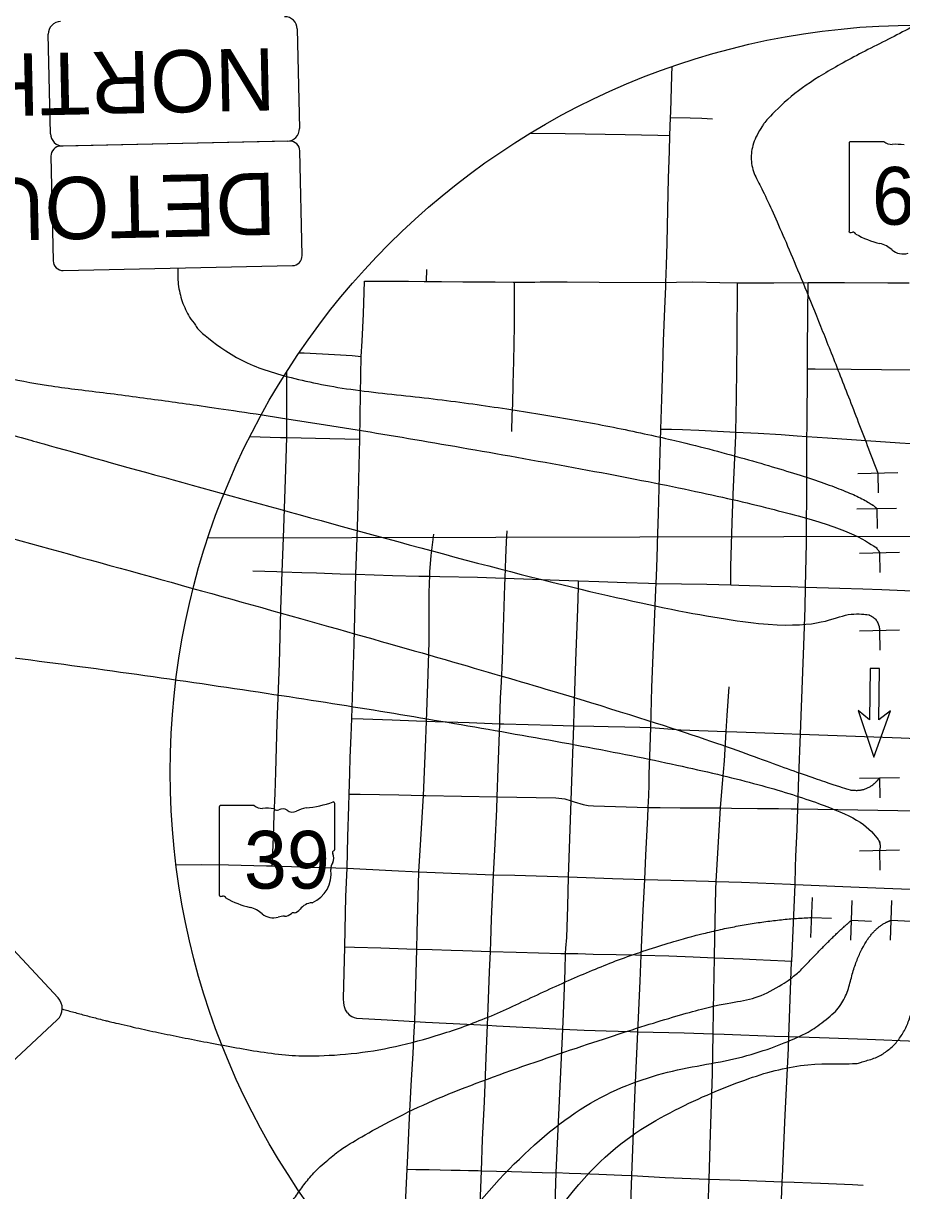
# Model space of a CAD drawing. Extents: x -15.3 to 34, y 0 to 22.
# Drawn here: x 5.535 to 9.062, y 14.569 to 19.257 of the extents above; entities that cross this region are included whole.
import ezdxf

# ---------------------------------------------------------------- set-up
doc = ezdxf.new("R2010")
doc.units = 0
for name, color, linetype in [('GM_X_City_Street', 7, 'Continuous'), ('GM_X_State_Route', 7, 'Continuous'), ('GM_X_State_Shield', 7, 'Continuous'), ('GM_X_Township', 7, 'Continuous'), ('PM_P_Cells', 7, 'Continuous'), ('SH_Text', 7, 'Continuous'), ('SN_P_Signs', 7, 'Continuous')]:
    doc.layers.add(name, color=color, linetype=linetype)

msp = doc.modelspace()

# ---------------------------------------------------------------- linework, layer by layer
at = {"layer": 'GM_X_City_Street'}
for p, q in [((7.1544, 18.2223), (7.1554, 18.2682)), ((6.5927, 17.5937), (6.5924, 17.8581))]:
    msp.add_line(p, q, dxfattribs=at)
for points in [[(8.1336, 18.8786), (8.1343, 18.9019), (8.1389, 19.0477), (8.1398, 19.0836)], [(8.1313, 18.8064), (8.1336, 18.8786)], [(8.1336, 18.8786), (8.2121, 18.8776), (8.2599, 18.8759), (8.3015, 18.8744)], [(7.5709, 18.8161), (7.7102, 18.8143), (7.9514, 18.8108), (8.0831, 18.8076), (8.1313, 18.8064)], [(8.1228, 18.5094), (8.1256, 18.6353), (8.1293, 18.7435), (8.1313, 18.8064)], [(8.1149, 18.2169), (8.1175, 18.2866), (8.1198, 18.3737), (8.1228, 18.5094)], [(6.8918, 17.9196), (6.8949, 17.9808), (6.9005, 18.0899), (6.9035, 18.1771), (6.9044, 18.2223)], [(6.9044, 18.2223), (6.9438, 18.222), (7.0203, 18.2215), (7.0809, 18.2211), (7.1446, 18.2206), (7.2143, 18.2201), (7.2992, 18.2195), (7.3689, 18.219), (7.4296, 18.2186), (7.5016, 18.2181), (7.5069, 18.2181)], [(7.4963, 17.6178), (7.4979, 17.6838), (7.5002, 17.7276), (7.5023, 17.8089), (7.5046, 17.8998), (7.5064, 17.9695), (7.5066, 18.0423), (7.5069, 18.1858), (7.5069, 18.2181)], [(7.5069, 18.2181), (7.5892, 18.2183), (7.6102, 18.2188), (7.7184, 18.2195), (7.8471, 18.2175), (8.1149, 18.2169)], [(8.0952, 17.6279), (8.0987, 17.7474), (8.1025, 17.8753), (8.1058, 17.9811), (8.1108, 18.1118), (8.1143, 18.1992), (8.1149, 18.2169)], [(8.1149, 18.2169), (8.1577, 18.2175), (8.2227, 18.2185), (8.3311, 18.2157), (8.4029, 18.2155)], [(8.3958, 17.6158), (8.3988, 17.7546), (8.4008, 17.9799), (8.4029, 18.2155)], [(8.4029, 18.2155), (8.5486, 18.2151), (8.6858, 18.2157)], [(8.6834, 17.8697), (8.6839, 17.9505), (8.6858, 18.2157)], [(8.6858, 18.2157), (8.8324, 18.2164), (9.0062, 18.2151), (9.0924, 18.2147)], [(6.6426, 17.9345), (6.6623, 17.934), (6.7843, 17.9274), (6.8552, 17.9225), (6.8918, 17.9196)], [(6.8862, 17.587), (6.8892, 17.7697), (6.8918, 17.9196)], [(8.6815, 17.5982), (8.6818, 17.6358), (8.6834, 17.8697)], [(8.6834, 17.8697), (8.714, 17.8694), (8.8594, 17.868), (8.9809, 17.8668), (9.0968, 17.8657)], [(6.4445, 17.5972), (6.568, 17.5943), (6.5927, 17.5937)], [(6.5744, 17.0543), (6.579, 17.191), (6.5869, 17.4253), (6.5927, 17.5937)], [(6.5927, 17.5937), (6.7658, 17.5895), (6.8862, 17.587)], [(6.875, 17.1923), (6.8792, 17.3197), (6.8862, 17.587)], [(8.0758, 17.0079), (8.0783, 17.0705), (8.0812, 17.1578), (8.0815, 17.1671), (8.0852, 17.2887), (8.0897, 17.4416), (8.0952, 17.6279)], [(8.0952, 17.6279), (8.1376, 17.6272), (8.1813, 17.6265), (8.2472, 17.6232), (8.3712, 17.6171), (8.3958, 17.6158)], [(8.3755, 17.0021), (8.3758, 17.0323), (8.3762, 17.0759), (8.3786, 17.1637), (8.381, 17.2515), (8.3847, 17.3651), (8.3955, 17.6016), (8.3958, 17.6158)], [(8.3958, 17.6158), (8.4861, 17.6114), (8.5774, 17.6052), (8.6427, 17.6009), (8.6815, 17.5982)], [(8.6759, 16.993), (8.6799, 17.1711), (8.6804, 17.4328), (8.6815, 17.5982)], [(8.6815, 17.5982), (8.7641, 17.5927), (9.055, 17.5722), (9.098, 17.5703), (9.0993, 17.5703)], [(7.4698, 17.0283), (7.4724, 17.1095), (7.4749, 17.1749), (7.4778, 17.2184)], [(6.8705, 17.0443), (6.8725, 17.1155), (6.875, 17.1917), (6.875, 17.1923)], [(7.1667, 17.0362), (7.1675, 17.0543), (7.1729, 17.1196), (7.1778, 17.1628), (7.1807, 17.1843), (7.1836, 17.2058)], [(6.4567, 17.0582), (6.5522, 17.055), (6.5744, 17.0543)], [(6.5345, 15.8728), (6.5366, 15.9255), (6.5392, 15.9913), (6.5422, 16.0779), (6.5455, 16.1634), (6.5488, 16.2501), (6.5545, 16.4459), (6.5632, 16.6858), (6.5693, 16.9035), (6.5744, 17.0543)], [(6.5744, 17.0543), (6.6537, 17.0516), (6.7116, 17.0496), (6.8069, 17.0465), (6.8705, 17.0443)], [(6.8533, 16.4652), (6.8629, 16.7651), (6.8705, 17.0443)], [(6.8705, 17.0443), (7.017, 17.0394), (7.1234, 17.0365), (7.1601, 17.0362), (7.1667, 17.0362)], [(7.1535, 16.4546), (7.1593, 16.6032), (7.1639, 16.7715), (7.1646, 16.9667), (7.1655, 17.0107), (7.1667, 17.0362)], [(7.1667, 17.0362), (7.2078, 17.0359), (7.3591, 17.0334), (7.4667, 17.0283), (7.4698, 17.0283)], [(7.4477, 16.4442), (7.4483, 16.4595), (7.4513, 16.5464), (7.4543, 16.612), (7.4591, 16.6983), (7.4634, 16.8295), (7.4689, 17.0003), (7.4698, 17.0283)], [(7.4698, 17.0283), (7.5796, 17.0245), (7.6869, 17.021), (7.7643, 17.0183)], [(7.7451, 16.4359), (7.7471, 16.494), (7.754, 16.6965), (7.7611, 16.9042), (7.7629, 16.9482), (7.7638, 16.9922), (7.7643, 17.0183)], [(7.7643, 17.0183), (7.8458, 17.0156), (7.9558, 17.0119), (8.0456, 17.0089), (8.0758, 17.0079)], [(8.0539, 16.4291), (8.0584, 16.5902), (8.0634, 16.7213), (8.0748, 16.9832), (8.0758, 17.0079)], [(8.0758, 17.0079), (8.28, 17.0049), (8.3755, 17.0021)], [(8.3755, 17.0021), (8.4076, 17.0011), (8.5377, 16.9972), (8.6158, 16.9948), (8.6759, 16.993)], [(8.6552, 16.402), (8.6578, 16.4755), (8.6683, 16.7582), (8.674, 16.9105), (8.6759, 16.993)], [(8.6759, 16.993), (8.8134, 16.9888), (8.9053, 16.9858), (8.9824, 16.9832), (9.1055, 16.9773)], [(8.3574, 16.4126), (8.3614, 16.4766), (8.3686, 16.592)], [(6.8433, 16.1615), (6.8458, 16.2437), (6.8476, 16.3088), (6.8511, 16.3953), (6.8533, 16.4652)], [(6.8533, 16.4652), (6.8995, 16.4636), (7.0153, 16.4594), (7.1137, 16.456), (7.1535, 16.4546)], [(7.1412, 16.1561), (7.1493, 16.3478), (7.1535, 16.4546)], [(7.1535, 16.4546), (7.1892, 16.4533), (7.3252, 16.4485), (7.4477, 16.4442)], [(7.4375, 16.1509), (7.4418, 16.2653), (7.4477, 16.4442)], [(7.4477, 16.4442), (7.464, 16.4438), (7.6597, 16.4378), (7.7451, 16.4359)], [(7.7348, 16.1345), (7.7363, 16.1756), (7.7451, 16.4359)], [(7.7451, 16.4359), (7.8257, 16.4341), (7.8837, 16.4328), (7.9503, 16.4314), (8.0109, 16.4301), (8.0539, 16.4291)], [(8.0438, 16.108), (8.0462, 16.1556), (8.0476, 16.1987), (8.0484, 16.2416), (8.0518, 16.3499), (8.0539, 16.4291)], [(8.0539, 16.4291), (8.1746, 16.419), (8.3574, 16.4126)], [(8.334, 16.1058), (8.3423, 16.2046), (8.3497, 16.2955), (8.3544, 16.3658), (8.3574, 16.4126)], [(8.3574, 16.4126), (8.3997, 16.4111), (8.5873, 16.4044), (8.6552, 16.402)], [(8.6445, 16.1027), (8.6492, 16.2333), (8.6552, 16.402)], [(8.6552, 16.402), (9.0599, 16.3877), (9.1238, 16.3853)], [(6.8346, 15.8644), (6.8383, 15.9898), (6.8419, 16.1132), (6.8433, 16.1615)], [(6.8433, 16.1615), (6.8876, 16.1608), (7.0428, 16.1583), (7.1412, 16.1561)], [(7.1225, 15.8497), (7.1304, 15.9791), (7.1412, 16.1561)], [(7.1412, 16.1561), (7.1511, 16.1559), (7.4375, 16.1509)], [(7.4227, 15.8371), (7.429, 15.9612), (7.4357, 16.1015), (7.4375, 16.1509)], [(7.4375, 16.1509), (7.6725, 16.1469), (7.7096, 16.1422), (7.7348, 16.1345)], [(7.7238, 15.8286), (7.7348, 16.1345)], [(7.7348, 16.1345), (7.7469, 16.1309), (7.7825, 16.1202), (7.8033, 16.1156), (7.8245, 16.1142), (8.0438, 16.108)], [(8.0298, 15.8185), (8.0338, 15.9157), (8.0419, 16.0686), (8.0438, 16.108)], [(8.0438, 16.108), (8.0919, 16.1076), (8.1729, 16.1069), (8.2655, 16.106), (8.334, 16.1058)], [(8.3166, 15.8106), (8.334, 16.1058)], [(8.334, 16.1058), (8.3778, 16.105), (8.4832, 16.1041), (8.5676, 16.1033), (8.6175, 16.1029), (8.6445, 16.1027)], [(8.6335, 15.799), (8.6359, 15.8678), (8.6374, 15.9114), (8.6417, 16.0198), (8.6445, 16.1027)], [(8.6445, 16.1027), (9.1269, 16.0939)], [(6.8256, 15.5485), (6.8304, 15.7507), (6.8346, 15.8644)], [(7.1148, 15.5389), (7.1168, 15.6055), (7.1213, 15.8), (7.1225, 15.8497)], [(7.4102, 15.5297), (7.4116, 15.5691), (7.4147, 15.6597), (7.4227, 15.8371)], [(7.7118, 15.5217), (7.7136, 15.5431), (7.717, 15.5854), (7.7214, 15.7094), (7.7238, 15.8286)], [(8.3098, 15.5042), (8.3111, 15.586), (8.3158, 15.7794), (8.3166, 15.8106)], [(8.6202, 15.4911), (8.6335, 15.799)], [(6.8361, 15.2827), (6.8291, 15.295), (6.825, 15.3072), (6.8221, 15.3224), (6.8207, 15.3399), (6.8256, 15.5463), (6.8256, 15.5485)], [(6.8256, 15.5485), (6.8652, 15.5472), (6.9708, 15.5437), (7.0743, 15.5402), (7.1148, 15.5389)], [(7.1065, 15.2478), (7.1148, 15.5389)], [(7.1148, 15.5389), (7.1763, 15.5368), (7.2534, 15.5343), (7.2998, 15.5328), (7.4102, 15.5297)], [(7.3987, 15.2328), (7.402, 15.3035), (7.4073, 15.4474), (7.4102, 15.5297)], [(7.4102, 15.5297), (7.5134, 15.5268), (7.6925, 15.5218), (7.7118, 15.5217)], [(7.7013, 15.217), (7.7041, 15.2793), (7.711, 15.4539), (7.7118, 15.5217)], [(7.7118, 15.5217), (7.7619, 15.5206), (7.8227, 15.5192), (7.9152, 15.5172), (7.9934, 15.5155), (8.0162, 15.515)], [(8.0162, 15.515), (8.1267, 15.512), (8.2251, 15.5078), (8.3098, 15.5042)], [(8.305, 15.1986), (8.3066, 15.2949), (8.3098, 15.5042)], [(8.3098, 15.5042), (8.3119, 15.5042), (8.4243, 15.4994), (8.4769, 15.4972), (8.5924, 15.4923), (8.6202, 15.4911)], [(8.6087, 15.1879), (8.6199, 15.486), (8.6202, 15.4911)], [(6.8361, 15.2827), (6.8431, 15.2746), (6.8542, 15.2682), (6.8635, 15.2641), (6.8728, 15.262), (6.9953, 15.2549), (7.1065, 15.2478)], [(7.0763, 14.6549), (7.0788, 14.7095), (7.0858, 14.8612), (7.0927, 14.9913), (7.0997, 15.1207), (7.1043, 15.208), (7.1065, 15.2478)], [(7.1065, 15.2478), (7.1493, 15.2451), (7.3987, 15.2328)], [(7.3745, 14.6489), (7.379, 14.7742), (7.3865, 14.9255), (7.3942, 15.1385), (7.3987, 15.2328)], [(7.3987, 15.2328), (7.435, 15.2311), (7.6992, 15.2171), (7.7013, 15.217)], [(7.6749, 14.641), (7.6803, 14.7577), (7.7013, 15.217)], [(7.7013, 15.217), (7.7871, 15.2134), (7.8749, 15.2113), (7.9713, 15.2078), (8.0024, 15.2066)], [(8.0024, 15.2066), (8.1888, 15.2027), (8.305, 15.1986)], [(8.2881, 14.6152), (8.2943, 14.7955), (8.3026, 15.0395), (8.305, 15.1986)], [(8.305, 15.1986), (8.349, 15.1971), (8.5517, 15.1899), (8.6087, 15.1879)], [(8.582, 14.6041), (8.5829, 14.6256), (8.5945, 14.8734), (8.6069, 15.1395), (8.6087, 15.1879)], [(8.6087, 15.1879), (8.7321, 15.1836), (8.9236, 15.1768), (9.1233, 15.1698)], [(7.0825, 14.1005), (7.071, 14.1266), (7.0619, 14.1638), (7.0603, 14.2329), (7.0608, 14.2696), (7.0617, 14.3414), (7.0644, 14.4004), (7.0763, 14.6549)], [(7.0763, 14.6549), (7.1112, 14.6542), (7.1647, 14.6532), (7.2083, 14.6524), (7.2528, 14.6516), (7.2887, 14.6509), (7.3225, 14.6502), (7.3612, 14.6495), (7.3745, 14.6489)], [(7.3504, 14.0624), (7.354, 14.162), (7.3696, 14.5121), (7.3745, 14.6489)], [(7.3745, 14.6489), (7.4948, 14.6452), (7.6187, 14.6413), (7.6595, 14.6401), (7.6749, 14.641)], [(7.6544, 14.0516), (7.6546, 14.1018), (7.6588, 14.1886), (7.6631, 14.2974), (7.6749, 14.641)], [(7.6749, 14.641), (7.7261, 14.639), (7.7736, 14.6371), (7.8452, 14.6343), (7.9381, 14.6306), (7.9779, 14.629)], [(7.9779, 14.629), (8.1125, 14.6214), (8.2839, 14.6153), (8.2881, 14.6152)], [(8.2668, 14.0392), (8.268, 14.0683), (8.2775, 14.2857), (8.2844, 14.505), (8.2881, 14.6152)], [(8.2881, 14.6152), (8.4126, 14.6103), (8.582, 14.6041)], [(8.5503, 14.0487), (8.5572, 14.0578), (8.5621, 14.0654), (8.5642, 14.0752), (8.569, 14.282), (8.5762, 14.4615), (8.582, 14.6041)], [(8.582, 14.6041), (8.6302, 14.6026), (8.6989, 14.6004), (8.7357, 14.5992), (8.8639, 14.5933), (8.9073, 14.5913)]]:
    msp.add_lwpolyline(points, dxfattribs=at)
at = {"layer": 'GM_X_State_Route'}
for points in [[(6.1482, 15.878), (6.249, 15.8782), (6.3581, 15.8773), (6.5108, 15.8735), (6.5345, 15.8728), (6.7288, 15.8671), (6.7438, 15.8667)], [(6.7438, 15.8667), (6.8346, 15.8644), (7.0144, 15.8548), (7.1225, 15.8497), (7.2213, 15.8451), (7.4227, 15.8371), (7.5089, 15.8353), (7.7238, 15.8286)], [(7.7238, 15.8286), (7.9007, 15.8227), (8.0298, 15.8185)], [(7.937, 13.5996), (7.9371, 13.6011), (7.9474, 13.8194), (7.9499, 13.8847), (7.955, 14.0147), (7.9559, 14.0497), (7.9573, 14.1015), (7.9631, 14.2541), (7.9738, 14.5163), (7.9779, 14.629), (7.9818, 14.7347), (7.9917, 14.9734), (8.0024, 15.2066), (8.0037, 15.2353), (8.0114, 15.4102), (8.0162, 15.515), (8.0204, 15.6067), (8.0242, 15.6938), (8.0298, 15.8185)], [(8.0298, 15.8185), (8.1868, 15.8144), (8.2865, 15.8115), (8.3166, 15.8106), (8.4184, 15.8074), (8.6157, 15.7997), (8.6335, 15.799), (8.8577, 15.7893), (8.9911, 15.7839)], [(8.9911, 15.7839), (9.1313, 15.7782)]]:
    msp.add_lwpolyline(points, dxfattribs=at)
at = {"layer": 'GM_X_State_Shield'}
for p, q in [((8.8503, 18.7759), (8.8503, 18.4237)), ((8.9907, 18.782), (8.8548, 18.782)), ((6.3211, 16.1092), (6.3211, 15.757)), ((6.4616, 16.1152), (6.3257, 16.1152)), ((6.7852, 15.9397), (6.7852, 16.124)), ((6.7851, 15.9398), (6.7852, 15.9397))]:
    msp.add_line(p, q, dxfattribs=at)
for centre, radius, start, end in [((8.8556, 18.7767), 0.00538, 98.1301, 188.1301), ((9.0231, 18.8229), 0.0521, 231.6195, 271.1119), ((9.0404, 18.5842), 0.1872, 80.4867, 94.9883), ((8.8556, 18.4229), 0.00542, 171.9584, 258.3066), ((8.8564, 18.459), 0.0414, 267.339, 280.6039), ((8.8649, 18.4034), 0.0149, 29.7484, 93.2717), ((9.0533, 18.7198), 0.3554, 240.4129, 257.1985), ((8.9474, 18.2655), 0.1112, 47.1842, 75.836), ((9.0676, 18.4016), 0.0706, 230.7004, 286.2918), ((6.6199, 16.5954), 0.4921, 275.8445, 288.9065), ((6.78, 16.1247), 0.00517, 351.8621, 97.738), ((6.3264, 16.1099), 0.00538, 98.1301, 188.1301), ((6.494, 16.1561), 0.0521, 231.6195, 271.1119), ((6.5113, 15.9175), 0.1872, 80.4867, 94.9883), ((6.5538, 16.1117), 0.015, 219.7921, 297.1024), ((6.5758, 16.071), 0.0313, 54.4667, 119.1411), ((6.6162, 16.1269), 0.0376, 233.8562, 294.8282), ((6.6827, 16.0077), 0.099, 97.3462, 120.7689), ((6.784, 15.9262), 0.00799, 107.944, 210.337), ((6.7331, 15.9029), 0.048, 340.033, 23.6496), ((6.7797, 15.939), 0.00553, 289.6038, 7.7341), ((6.6475, 15.8392), 0.1231, 292.3089, 8.9858), ((6.8037, 15.8626), 0.0349, 136.8065, 186.9296), ((6.3265, 15.7562), 0.00542, 171.9584, 258.3066), ((6.3273, 15.7922), 0.0414, 267.339, 280.6039), ((6.3358, 15.7366), 0.0149, 29.7484, 93.2717), ((6.5242, 16.0531), 0.3554, 240.4129, 257.1985), ((6.6994, 15.6581), 0.0674, 94.4031, 142.5768), ((6.4183, 15.5987), 0.1112, 47.1842, 75.836), ((6.5385, 15.7349), 0.0706, 230.7004, 286.2918), ((6.5793, 15.6131), 0.058, 85.6951, 111.2099), ((6.5844, 15.7085), 0.0376, 268.777, 315.5493), ((6.6185, 15.6744), 0.0106, 65.7517, 132.6484), ((6.6139, 15.7228), 0.0398, 282.8732, 323.2771)]:
    msp.add_arc(centre, radius, start, end, dxfattribs=at)
at = {"layer": 'GM_X_Township'}
msp.add_line((6.2762, 17.1903), (11.9695, 17.2034), dxfattribs=at)
at = {"layer": 'PM_P_Cells'}
for p, q in [((8.9348, 16.6659), (8.9331, 16.4596)), ((8.9723, 16.6655), (8.9348, 16.6659)), ((8.9535, 16.6657), (8.9535, 16.6657)), ((8.9706, 16.4593), (8.9723, 16.6655)), ((8.9331, 16.4596), (8.887, 16.4975)), ((8.887, 16.4975), (8.9506, 16.3095)), ((8.9506, 16.3095), (9.0172, 16.4964)), ((9.0172, 16.4964), (8.9706, 16.4593)), ((8.9506, 16.3095), (8.9506, 16.3095))]:
    msp.add_line(p, q, dxfattribs=at)
at = {"layer": 'SH_Text'}
msp.add_circle((9.125, 16.25), 3, dxfattribs=at)
for points in [[(9.492, 19.6955), (9.5648, 19.4628), (8.3529, 18.8728), (8.6057, 18.3944), (8.9661, 17.4512)], [(4.1592, 18.2966), (4.7515, 17.8162), (5.7312, 17.533), (8.5118, 16.773), (8.9677, 16.9331), (8.973, 16.8191)], [(2.759, 18.259), (3.2529, 17.7067), (4.0517, 17.5875), (7.8335, 16.5399), (8.7455, 16.2122), (8.9206, 16.1567), (8.973, 16.2268)], [(4.9569, 18.2744), (4.9232, 17.8865), (6.5628, 17.6894), (8.9216, 17.2583), (8.973, 17.1313)], [(6.1553, 18.2744), (6.1324, 17.8618), (7.7613, 17.6894), (8.8872, 17.3862), (8.9615, 17.3087)], [(2.2958, 17.6404), (2.4287, 18.163), (3.5269, 16.9468), (6.4522, 16.5976), (9.0269, 16.1255), (8.973, 15.936)], [(5.691, 15.2986), (5.9959, 15.21), (6.9618, 15.0455), (8.1962, 15.6458), (8.7004, 15.6657)], [(5.798, 12.8402), (6.2851, 12.6607), (7.5039, 14.9406), (8.7958, 15.1566), (8.904, 15.6179), (9.0202, 15.6546)], [(5.798, 14.0179), (6.2727, 14.0179), (6.5072, 14.3807), (6.828, 14.819), (8.2064, 15.3002), (8.557, 15.3486), (8.7927, 15.5985), (8.8602, 15.6546)], [(5.798, 11.6248), (6.3175, 11.4183), (7.5535, 14.563), (8.511, 15.0934), (9.0764, 15.0634), (9.1523, 15.6418), (9.3083, 15.6391)]]:
    msp.add_open_spline(points, degree=2, dxfattribs=at)
at = {"layer": 'SN_P_Signs'}
for p, q in [((6.6349, 19.2349), (6.6434, 18.835)), ((5.6436, 18.8136), (5.6351, 19.2135)), ((6.5945, 18.7839), (5.6947, 18.7646)), ((8.8861, 17.4495), (9.0461, 17.4529)), ((8.9661, 17.4512), (8.9678, 17.3712)), ((8.8815, 17.307), (9.0414, 17.3104)), ((8.9615, 17.3087), (8.9632, 17.2287)), ((8.893, 17.1296), (9.053, 17.133)), ((8.973, 17.1313), (8.9747, 17.0513)), ((8.893, 16.8174), (9.053, 16.8208)), ((8.973, 16.8191), (8.9747, 16.7391)), ((8.893, 16.2251), (9.053, 16.2286)), ((8.973, 16.2268), (8.9747, 16.1469)), ((8.893, 15.9343), (9.053, 15.9377)), ((8.973, 15.936), (8.9747, 15.8561)), ((8.6976, 15.5858), (8.7031, 15.7457)), ((8.8575, 15.5747), (8.863, 15.7346)), ((9.0174, 15.5747), (9.0229, 15.7346)), ((8.7004, 15.6657), (8.7803, 15.6629)), ((8.8602, 15.6546), (8.9402, 15.6518)), ((9.0202, 15.6546), (9.1001, 15.6518))]:
    msp.add_line(p, q, dxfattribs=at)
for points in [[(6.6045, 18.7841), (5.6847, 18.7644)], [(5.6456, 18.7236), (5.6546, 18.3037)], [(6.6543, 18.3251), (6.6453, 18.745)], [(5.6954, 18.2645), (6.6152, 18.2842)], [(5.0773, 15.9832), (5.6742, 15.3434)], [(5.6712, 15.2551), (5.0313, 14.6582)]]:
    msp.add_lwpolyline(points, dxfattribs=at)
for centre, radius, start, end in [((6.5849, 19.2338), 0.05, 1.2264, 91.2264), ((5.6851, 19.2146), 0.05, 91.2264, 181.2264), ((5.6937, 18.8147), 0.05, 181.2264, 271.2264), ((6.5934, 18.8339), 0.05, 271.2264, 1.2264), ((5.6856, 18.7244), 0.04, 91.2264, 181.2264), ((6.6053, 18.7441), 0.04, 1.2264, 91.2264), ((5.6945, 18.3045), 0.04, 181.2264, 271.2264), ((6.6143, 18.3242), 0.04, 271.2264, 1.2264), ((5.6285, 15.3008), 0.0625, 313.0119, 43.0119)]:
    msp.add_arc(centre, radius, start, end, dxfattribs=at)

# ---------------------------------------------------------------- texts
at = {"layer": 'GM_X_State_Shield'}
for s, p in [('60', (8.9423, 18.4485)), ('39', (6.4205, 15.7818))]:
    msp.add_text(s, height=0.23203, dxfattribs=at).set_placement(p)
at = {"layer": 'SN_P_Signs'}
for s, p in [('NORTH', (6.5431, 19.1579)), ('DETOUR', (6.5456, 18.6578))]:
    msp.add_text(s, height=0.25, rotation=181.2264, dxfattribs=at).set_placement(p)

doc.saveas('drawing.dxf')
